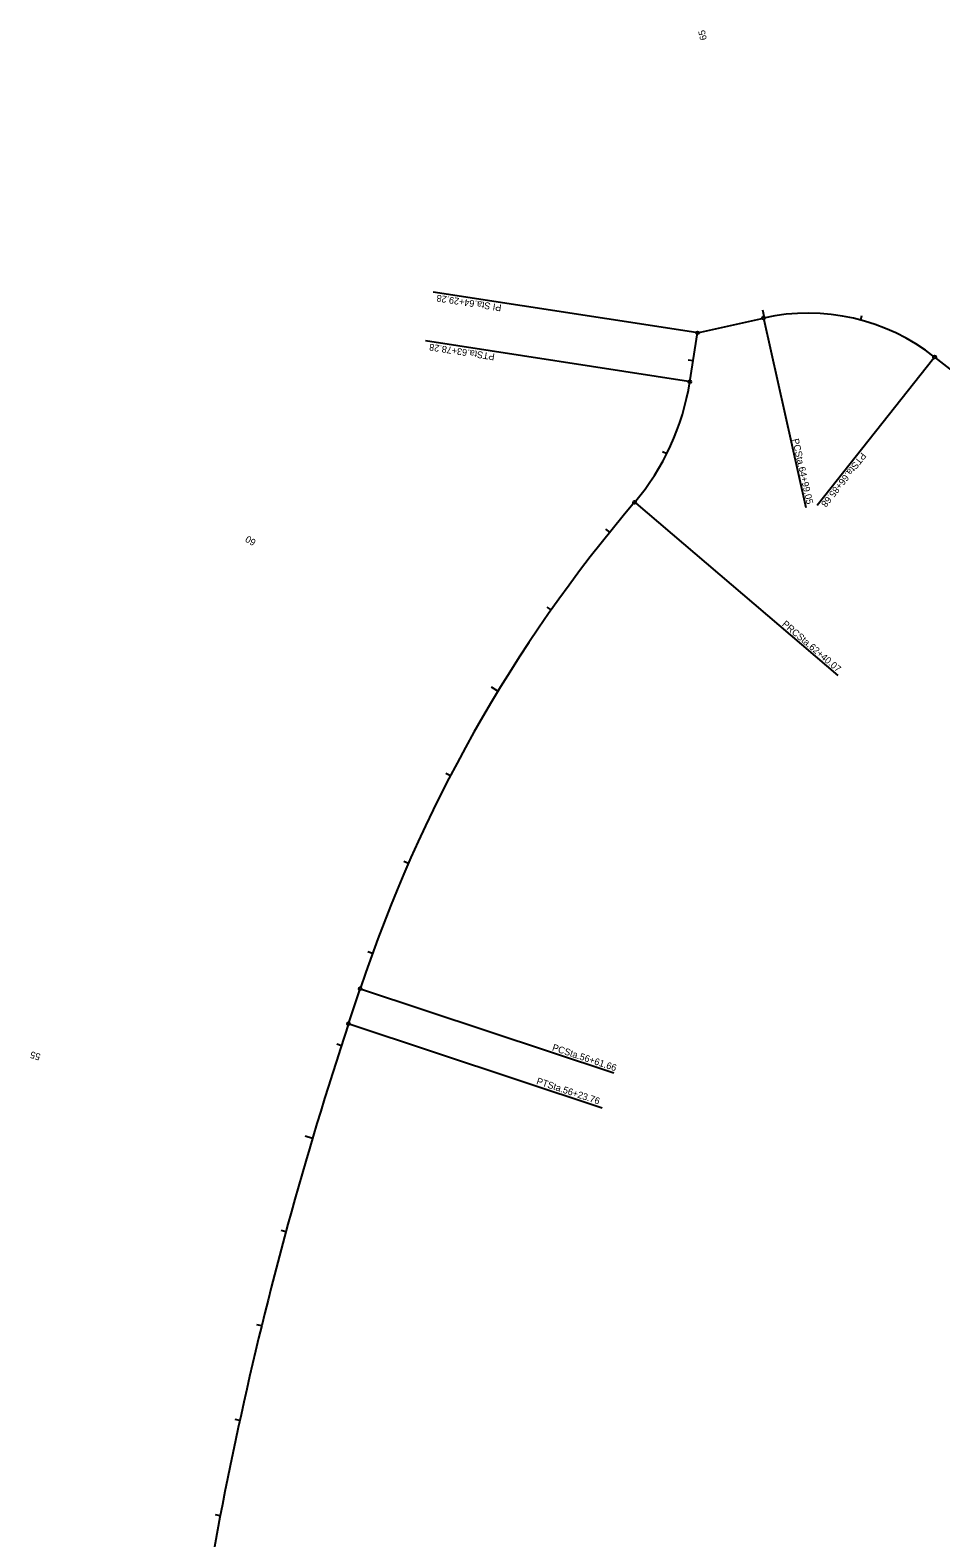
# Model space of a CAD drawing. Extents: x 554184 to 558768, y 503077 to 507235.
# Drawn here: x 557006 to 557943, y 505683 to 507235 of the extents above; entities that cross this region are included whole.
import ezdxf

# ---------------------------------------------------------------- set-up
doc = ezdxf.new("R2010")
doc.units = 0
for name, color, linetype in [('Default', 7, 'Continuous'), ('Prop Horizontal Alignment Station Label', 7, 'Continuous'), ('Prop Horizontal Alignment Tick Label', 7, 'Continuous'), ('Prop Horizontal Alignment Tick Large', 7, 'Continuous'), ('Prop Horizontal Alignment Tick Small', 7, 'Continuous'), ('Prop Vertical Profile Grade', 7, 'Continuous')]:
    doc.layers.add(name, color=color, linetype=linetype)

msp = doc.modelspace()

# ---------------------------------------------------------------- linework, layer by layer
at = {"layer": 'Default'}
msp.add_line((557684.8, 506872.7), (557692.6, 506923.1), dxfattribs=at)
for centre, radius, start, end in [((557806.5, 506733.4), 210, 51.6978, 102.6169), ((557437.7, 506910.8), 250, 319.5426, 351.2186), ((558769.3, 505775.3), 1500, 139.5426, 161.6362), ((561130, 504951.7), 4000, 161.6362, 173.9875)]:
    msp.add_arc(centre, radius, start, end, dxfattribs=at)
at = {"layer": 'Prop Horizontal Alignment Station Label'}
for p, q in [((557691.1, 506923.3), (557420.8, 506965.1)), ((557761, 506936.9), (557804.3, 506743.3)), ((557683.3, 506872.9), (557413, 506914.7)), ((557935.8, 506897), (557815.8, 506745.2)), ((557629.1, 506747.6), (557837.2, 506570.2)), ((557347.1, 506247.4), (557606.7, 506161.2)), ((557335.2, 506211.4), (557594.7, 506125.3))]:
    msp.add_line(p, q, dxfattribs=at)
for centre in [(557760.7, 506938.3), (557692.6, 506923.1), (557936.7, 506898.2), (557684.8, 506872.7), (557628, 506748.6), (557345.7, 506247.9), (557333.7, 506211.9)]:
    msp.add_circle(centre, 1.5, dxfattribs=at)
at = {"layer": 'Prop Horizontal Alignment Tick Large'}
for p, q in [((557761.6, 506938.5), (557759.9, 506946.3)), ((557487.4, 506554.3), (557480.6, 506558.5)), ((557296.6, 506093.9), (557288.9, 506096.1))]:
    msp.add_line(p, q, dxfattribs=at)
at = {"layer": 'Prop Horizontal Alignment Tick Small'}
for p, q in [((557860.6, 506936.3), (557861.9, 506941.1)), ((557688.1, 506894.1), (557683.2, 506894.9)), ((557661, 506798.4), (557656.6, 506800.7)), ((557602.4, 506717.8), (557598.5, 506720.9)), ((557542.2, 506638), (557538.1, 506640.8)), ((557438.4, 506467.2), (557433.9, 506469.5)), ((557395.2, 506377), (557390.7, 506379)), ((557358.2, 506284.1), (557353.5, 506285.8)), ((557326.3, 506189.3), (557321.6, 506190.9)), ((557269.2, 505997.7), (557264.4, 505999)), ((557244.3, 505900.8), (557239.4, 505902)), ((557221.8, 505803.4), (557216.9, 505804.5)), ((557201.7, 505705.4), (557196.8, 505706.4))]:
    msp.add_line(p, q, dxfattribs=at)
at = {"layer": 'Prop Vertical Profile Grade'}
for p, q in [((557692.6, 506923.1), (557760.7, 506938.3)), ((557684.8, 506872.7), (557692.6, 506923.1)), ((557936.7, 506898.2), (558219.1, 506675.1)), ((557333.7, 506211.9), (557345.7, 506247.9))]:
    msp.add_line(p, q, dxfattribs=at)
for centre, radius, start, end in [((557806.5, 506733.4), 210, 51.6978, 102.6169), ((557437.7, 506910.8), 250, 319.5426, 351.2186), ((558769.3, 505775.3), 1500, 139.5426, 161.6362), ((561130, 504951.7), 4000, 161.6362, 173.9875)]:
    msp.add_arc(centre, radius, start, end, dxfattribs=at)

# ---------------------------------------------------------------- texts
at = {"layer": 'Prop Horizontal Alignment Station Label'}
for s, rotation, p in [('PI Sta.64+29.28', 171.2186, (557491.4, 506952.1)), ('PTSta.63+78.28', 171.2186, (557484.4, 506901.6)), ('PCSta.64+99.05', 282.6169, (557790, 506813.4)), ('PTSta.66+85.68', 231.6978, (557861.5, 506800.5)), ('PRCSta.62+40.07', 319.5426, (557779.1, 506622.3)), ('PCSta.56+61.66', 341.6362, (557542.6, 506184.6)), ('PTSta.56+23.76', 341.6362, (557526.4, 506150))]:
    msp.add_text(s, height=7, rotation=rotation, dxfattribs=at).set_placement(p)
at = {"layer": 'Prop Horizontal Alignment Tick Label'}
for s, rotation, p in [('65', 102.358, (557702.4, 507225.1)), ('60', 148.7126, (557239.1, 506709.3)), ('55', 163.4089, (557017.3, 506180.7))]:
    msp.add_text(s, height=7, rotation=rotation, dxfattribs=at).set_placement(p)

doc.saveas('drawing.dxf')
